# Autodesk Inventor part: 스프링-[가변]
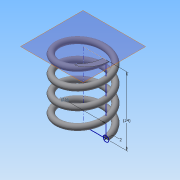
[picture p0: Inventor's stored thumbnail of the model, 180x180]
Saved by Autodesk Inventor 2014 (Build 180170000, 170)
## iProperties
Created: 2015-04
Part Number: 스프링-[가변]
Material: Generic
Document SubType Name: Modeling
Designer: Administrator
Density: 1 g/cm^3
Appearance: Default
Mass: 0.60807 g
Surface Area: 12.5277 cm^2
Volume: 0.60807 cm^3
Author: Administrator
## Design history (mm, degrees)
sketch "스케치1"
  geometry: L1 (0, 0)-(8, 0); L2 (8, 0)-(8, 11.5); L3 (8, 11.5)-(0, 11.5); L4 (0, 11.5)-(0, 0); C1 r 1 at (8, 0)
  constraints: 8 end point, 2 parallel, 1 centre point, 1 coincident, 1 horizontal, 1 perpendicular
  dimensions: "d0" = 16 diameter of L2 L4; "d1" = 11.50049 distance between parallel lines of L1 L3 (derived); "d2" = 2 diameter of C1
feature "코일1" pitch "d3" = 10; turns "d5" = 4; dims "d4" = 11.50049 (= d1), "d6" = 0, angle "d7" = 90 deg, angle "d8" = 90 deg, "d9" = 0, "d10" = 0
sketch "스케치2"
  geometry: L1 (-9, 0)-(-7, 0) reference; 1 further point
  constraints: 1 horizontal alignment
extrude "돌출1" cut sketch "스케치2" stored distance "d11" = 10; taper "d12" = 0 deg
node "작업 평면1"
sketch "스케치3"
  geometry: L1 (9, 0)-(7, 0) reference; 1 further point
  constraints: 1 horizontal alignment
extrude "돌출2" cut sketch "스케치3" stored distance "d13" = 10; taper "d14" = 0 deg
node "솔리드1"
node "절단 모서리 투영1"
node "절단 모서리 투영2"
